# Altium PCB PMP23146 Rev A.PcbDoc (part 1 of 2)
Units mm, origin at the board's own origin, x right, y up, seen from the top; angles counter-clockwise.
Board outline 35 x 30 mm, 4 copper layers (Top Layer, Int1 (GND), Int2 (PWR), Bottom Layer), stack 0.912 mm thick; 72 components, 51 nets, 255 pads, 53 vias.
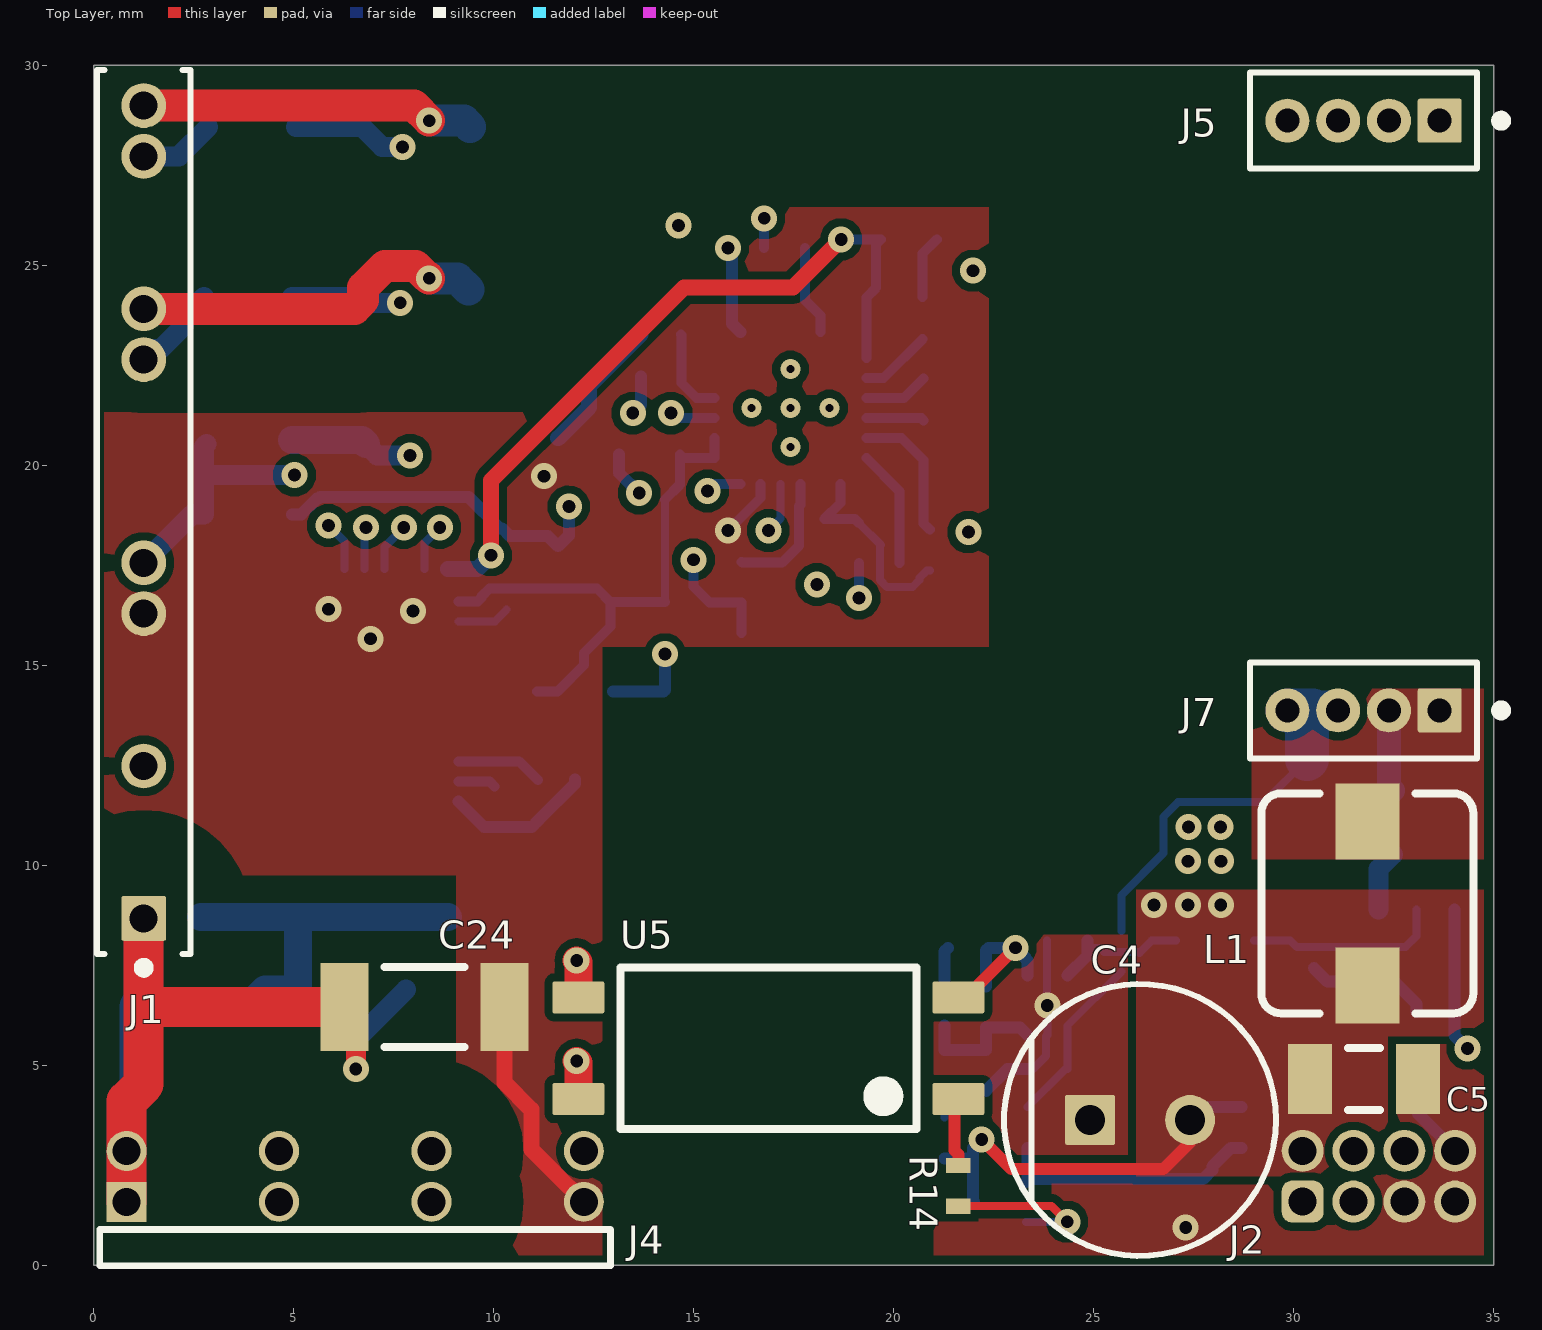
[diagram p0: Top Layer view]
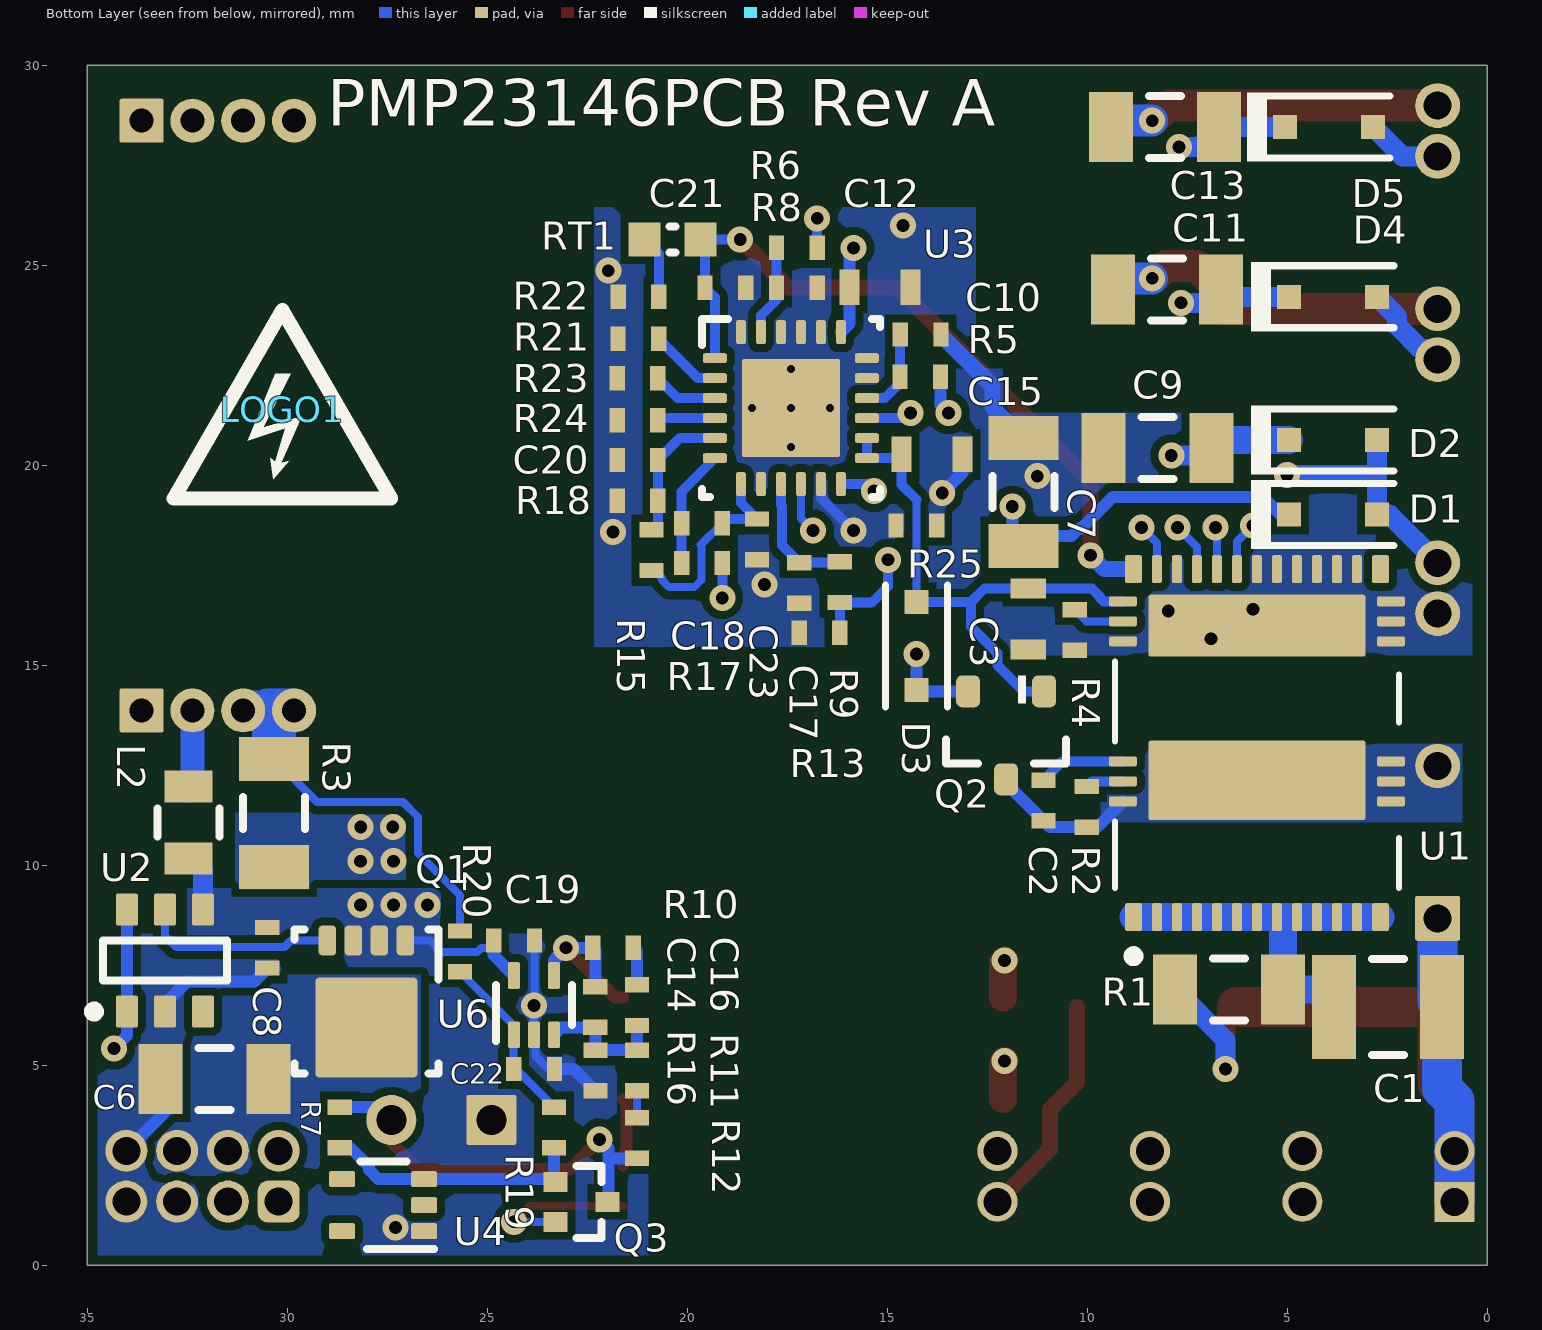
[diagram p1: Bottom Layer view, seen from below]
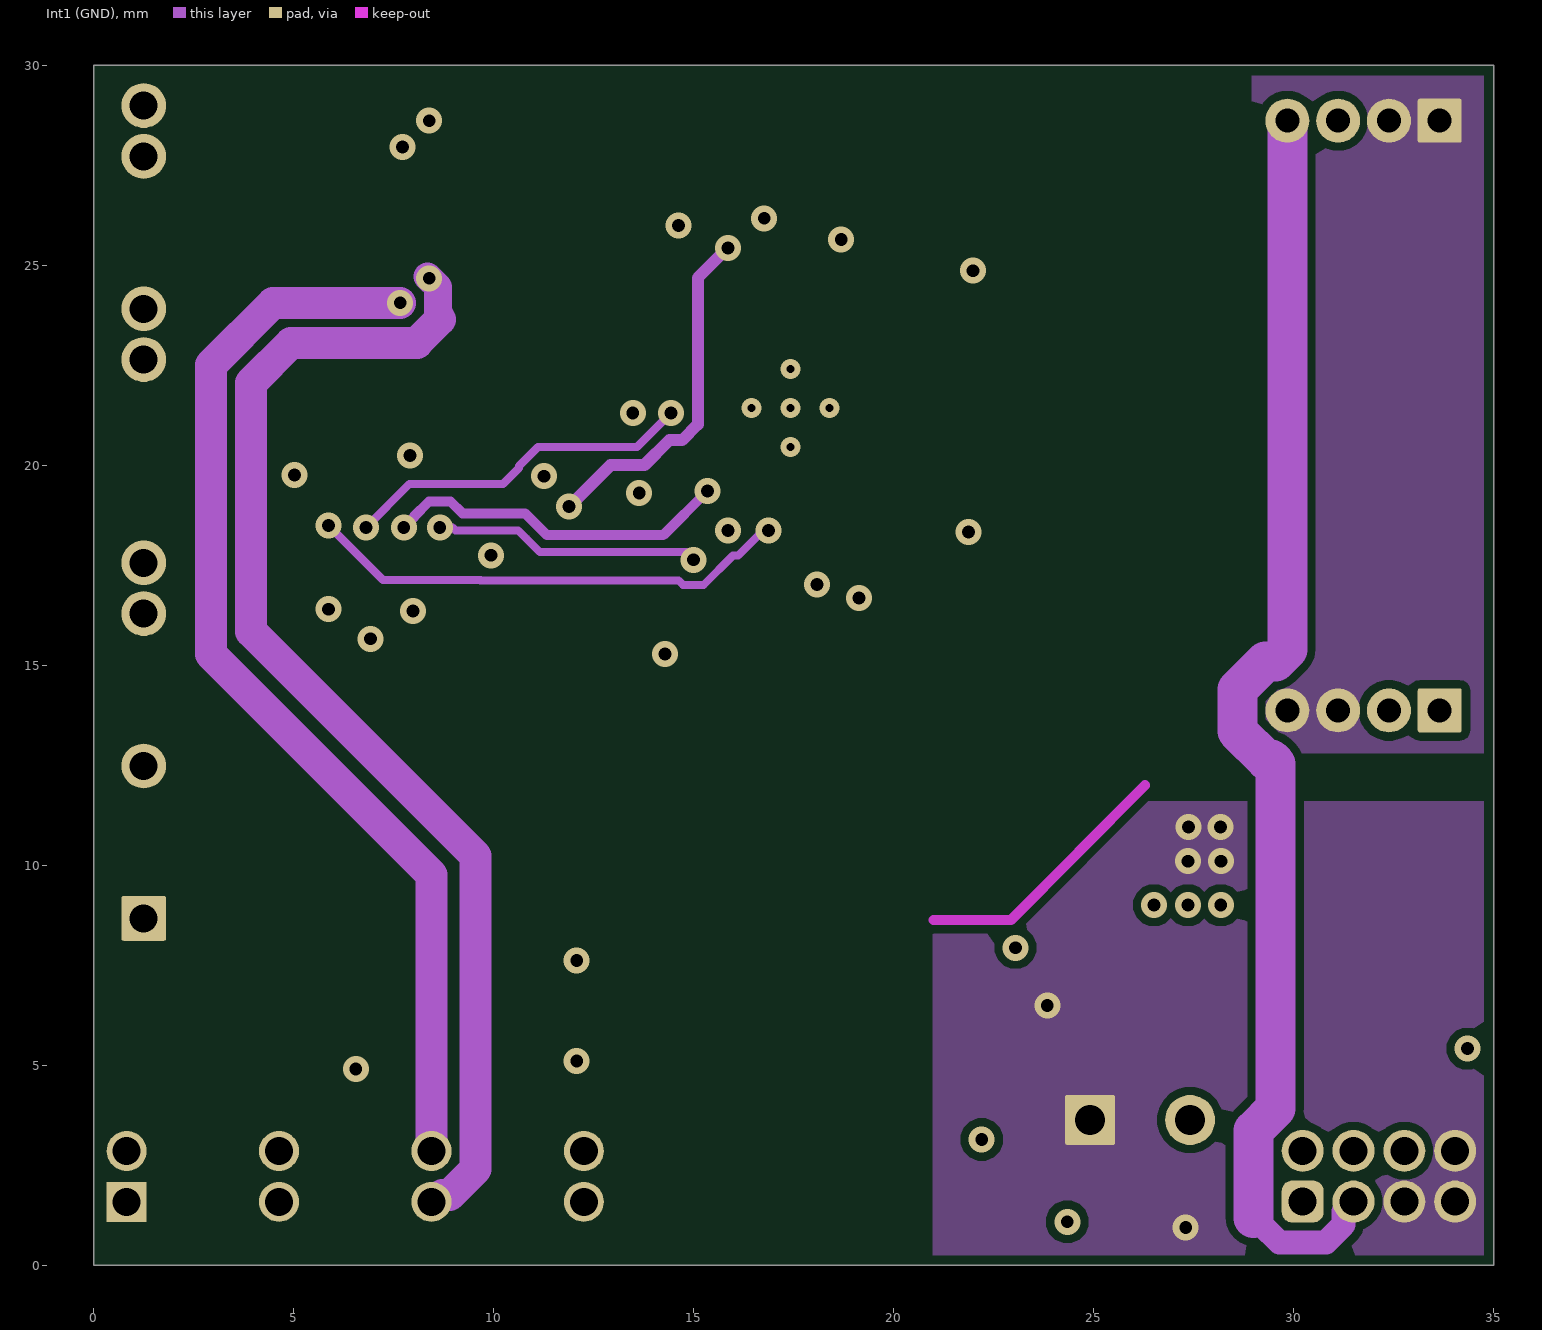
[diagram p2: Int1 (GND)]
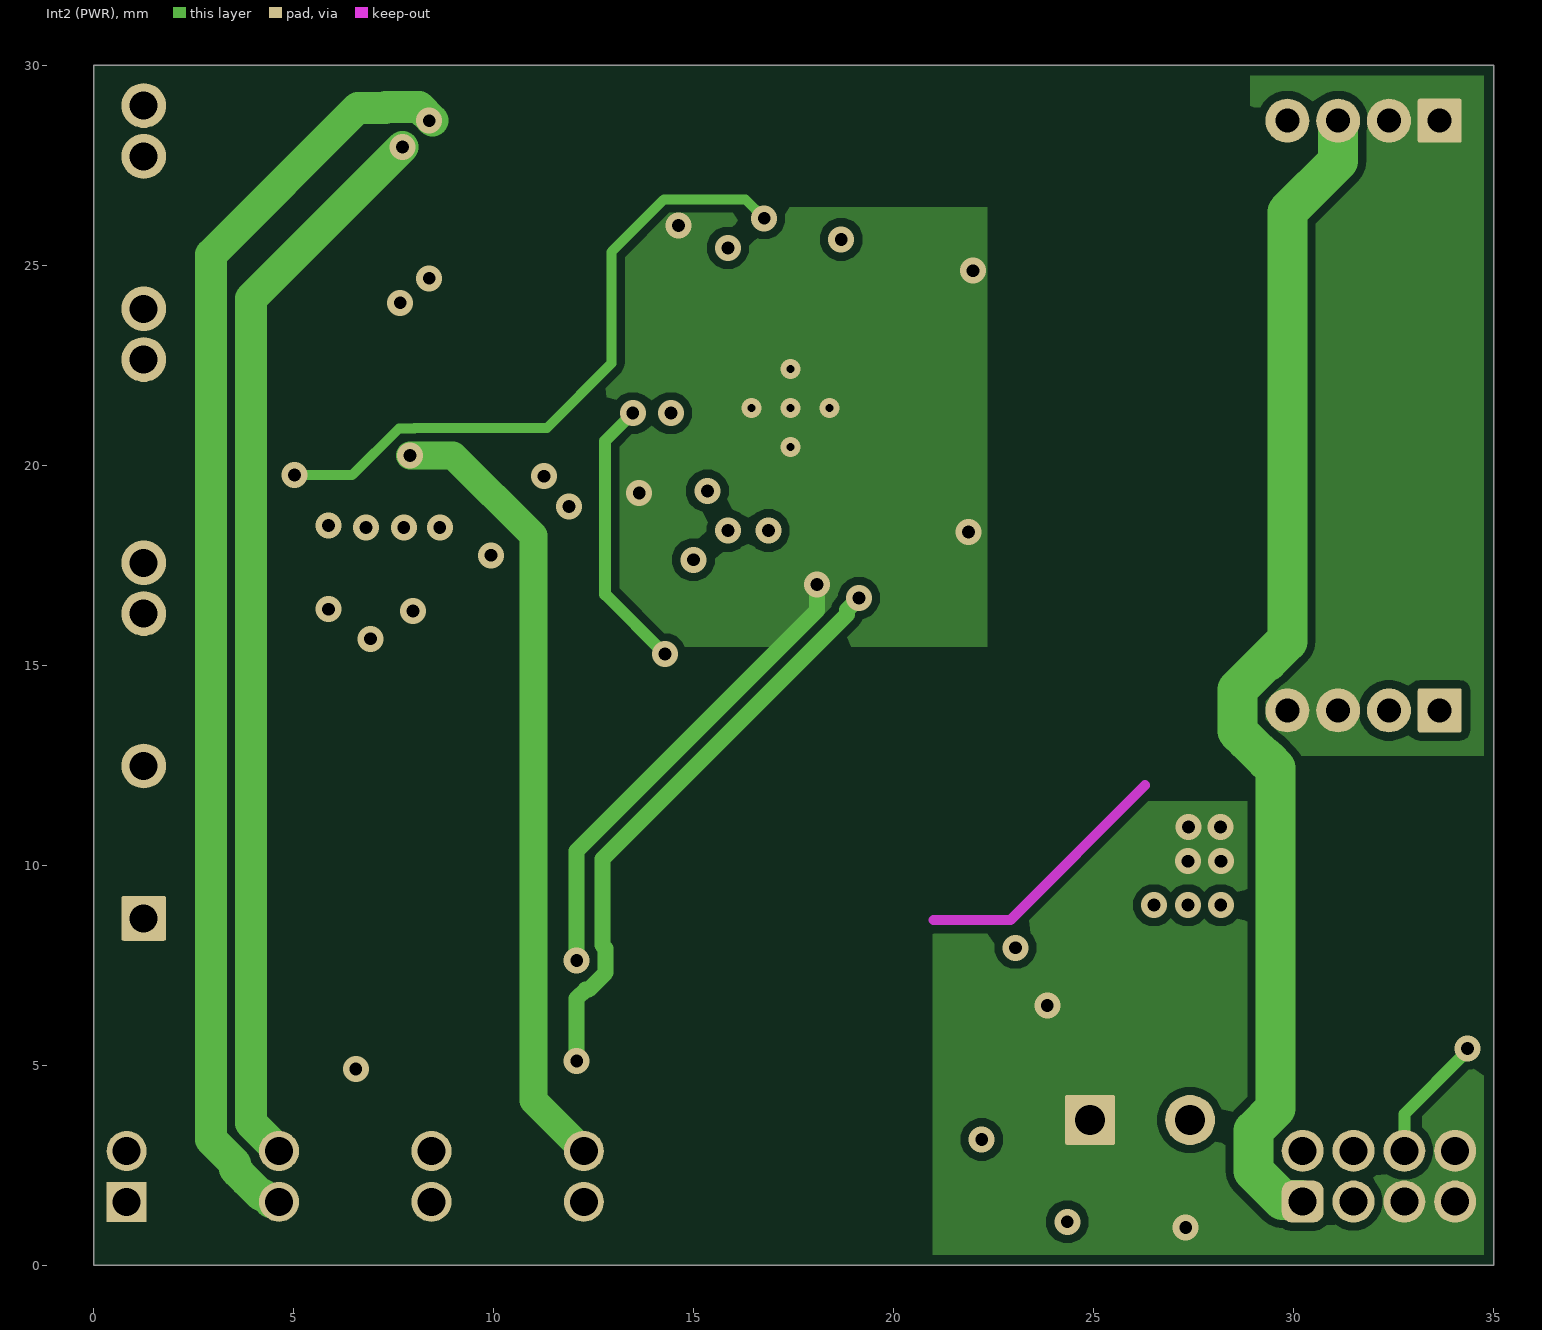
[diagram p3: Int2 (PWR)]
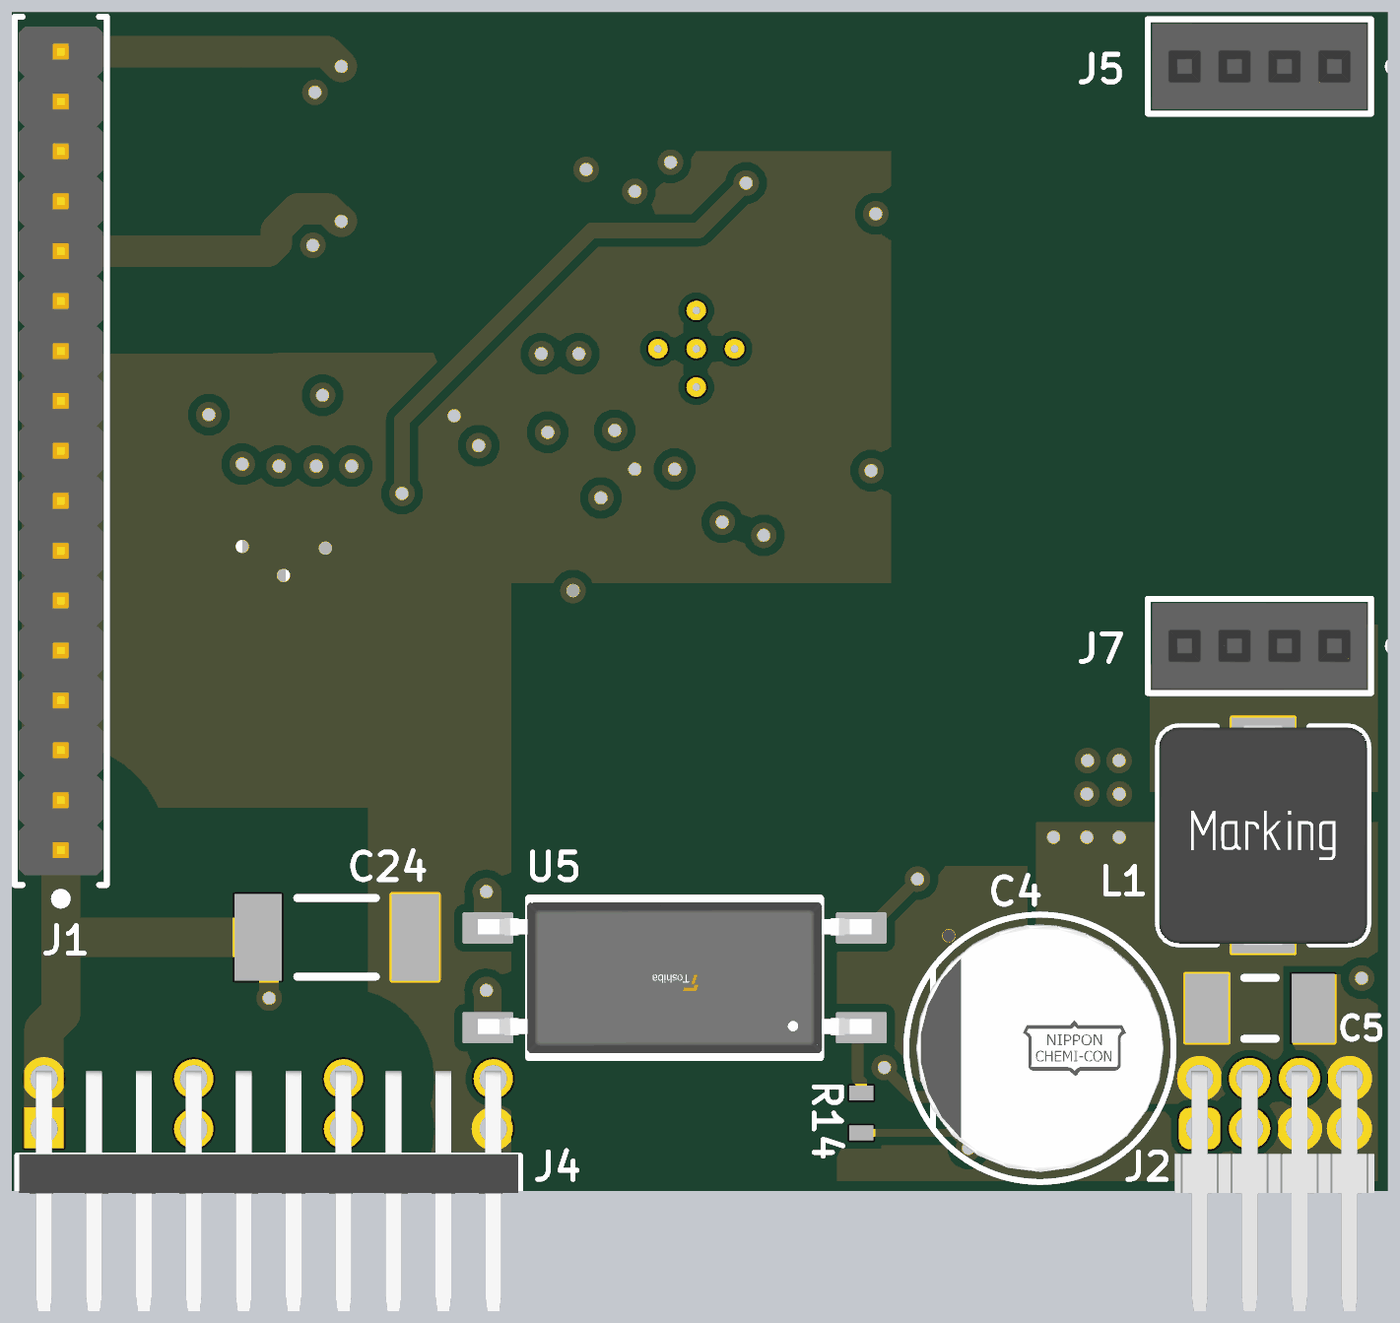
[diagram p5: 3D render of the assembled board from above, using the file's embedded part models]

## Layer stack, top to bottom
Top Solder: solder mask 0.0254, SM-001, Dk 4
Top Layer: signal copper 0.035
Dielectric 1: prepreg 0.1295, PP-017, Dk 4.3
Dielectric 2: prepreg 0.1295, PP-017, Dk 4.3
Int1 (GND): signal copper 0.035
Dielectric 3: core 0.254, Core-028, Dk 4.3
Int2 (PWR): signal copper 0.035
Dielectric 4: prepreg 0.1295, PP-017, Dk 4.3
Dielectric 5: prepreg 0.1295, PP-017, Dk 4.3
Bottom Layer: signal copper 0.035
Bottom Solder: solder mask 0.0254, SM-001, Dk 4

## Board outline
0,0 35,0 35,30 0,30

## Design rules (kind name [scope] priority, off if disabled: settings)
AcuteAngle [All] p1: minimum=5.00000000000000E+0000 checktracksonly=FALSE
AssemblyTestPointUsage [All] p1: valid=2
BoardOutlineClearance BoardOutlineClearance_Pri [InNet('P')] p1: gap=0.4 ignorepadtopadclearanceinfootprint=FALSE
BoardOutlineClearance BoardOutlineClearance_MountingHoles [OnCopper and InComponentClass('Mounting Holes')] p2: gap=0.635 ignorepadtopadclearanceinfootprint=FALSE
BoardOutlineClearance BoardOutlineClearance_Poly [OnCopper and InPoly] p3: gap=0.25 ignorepadtopadclearanceinfootprint=FALSE
BoardOutlineClearance [OnCopper and Not InComponentClass('Logo') and not InComponentClass('FiducialMark') and not InRegion(1000,500,4000,800)] p4: gap=0.25 ignorepadtopadclearanceinfootprint=FALSE
Clearance "Pri To Sec Inner Layers" [InNet('S') vs InNet('A')  Or InNet('B')] p1: gap=0.5 ignorepadtopadclearanceinfootprint=TRUE
Clearance "400V Clearance" [(InNetClass('400V') AND (OnTopLayer Or OnBottomLayer)) vs (InNetClass('Primary LV'))] p2: gap=2.2 ignorepadtopadclearanceinfootprint=TRUE
Clearance "Float Bias Clearance" [(InNetClass('BIAS_FLOAT') AND (OnTopLayer Or OnBottomLayer)) vs (InNetClass('Primary LV'))] p3: gap=2.2 ignorepadtopadclearanceinfootprint=TRUE
Clearance Clearance_Keepouts [((IsTrack Or IsArc) And Not InPoly) And IsFree and IsKeepOut vs ((IsTrack Or IsArc) And Not InPoly) And IsFree and IsKeepOut] p4: gap=0 ignorepadtopadclearanceinfootprint=TRUE
Clearance Clearance_Poly [InPolygon] p5: gap=0.203 ignorepadtopadclearanceinfootprint=TRUE except(0: Arc-Hole Track-Hole SMDPad-Hole THPad-Hole Via-Hole Fill-Hole Poly-Hole Region-Hole Text-Hole)
Clearance [All] p6: gap=0.2 ignorepadtopadclearanceinfootprint=TRUE except(0: Arc-Hole Track-Hole SMDPad-Hole THPad-Hole Via-Hole Fill-Hole Poly-Hole Region-Hole Text-Hole)
ComponentClearance ComponentClearance_MountingHoles_FiducialMarks [InComponentClass('Mounting Holes') vs InComponentClass('FiducialMark')] p1: gap=1.27 collisioncheckmode=3 verticalgap=0.254 showdistances=FALSE
ComponentClearance ComponentClearance_Shunt [InComponentClass('Header') vs InComponentClass('Shunt')] p2: gap=0 collisioncheckmode=3 verticalgap=0 showdistances=FALSE
ComponentClearance ComponentClearance_Logo [InComponentClass('Logo')] p3: gap=1.27 collisioncheckmode=3 verticalgap=0.254 showdistances=FALSE
ComponentClearance ComponentClearance_ScrewToNut [(HasFootprint('NY PMS 440 0025 PH')) vs (HasFootprint('Keystone_1902C'))] p4: gap=0.127 collisioncheckmode=3 verticalgap=0.254 showdistances=FALSE
ComponentClearance ComponentClearance_MountingHoles [InComponentClass('Mounting Holes')] p5: gap=6.35 collisioncheckmode=3 verticalgap=2540 showdistances=FALSE
ComponentClearance ComponentClearance_SmallPassives [HasFootprint('0201*') or HasFootprint('0402*') or HasFootprint('0508') or HasFootprint('0603*') or HasFootprint('0612') or HasFootprint('0805*') or HasFootprint('0815*') or HasFootprint('0830*') or HasFootprint('1206*') or HasFootprint('1210*') or HasFootprint('1808*') or HasFootprint('1812*') or HasFootprint('1825*') or HasFootprint('2010*') or HasFootprint('2220*') or HasFootprint('2225*') or HasFootprint('2512*') or HasFootprint('2728*') or HasFootprint('3518*') vs HasFootprint('0201*') or HasFootprint('0402*') or HasFootprint('0508') or HasFootprint('0603*') or HasFootprint('0612') or HasFootprint('0805*') or HasFootprint('0815*') or HasFootprint('0830*') or HasFootprint('1206*') or HasFootprint('1210*') or HasFootprint('1808*') or HasFootprint('1812*') or HasFootprint('1825*') or HasFootprint('2010*') or HasFootprint('2220*') or HasFootprint('2225*') or HasFootprint('2512*') or HasFootprint('2728*') or HasFootprint('3518*')] p6: gap=0.38 collisioncheckmode=3 verticalgap=0.254 showdistances=FALSE
ComponentClearance ComponentClearance_THtoSMT [IsThruComponent vs IsSMTComponent] p7: gap=0.381 collisioncheckmode=3 verticalgap=0.762 showdistances=FALSE
ComponentClearance ComponentClearance_THtoTH [IsThruComponent vs IsThruComponent] p8: gap=0.381 collisioncheckmode=3 verticalgap=0.762 showdistances=FALSE
ComponentClearance [All] p9: gap=0.381 collisioncheckmode=3 verticalgap=0.254 showdistances=FALSE
DiffPairsRouting [All] p1: maxlimit=2.54 minlimit=0.254 mostfreqgap=0.254 toplayer_minwidth=0.381 toplayer_maxwidth=0.381 toplayer_prefwidth=0.381 midlayer1_minwidth=0.381 midlayer1_maxwidth=0.381 midlayer1_prefwidth=0.381 midlayer2_minwidth=0.381 midlayer2_maxwidth=0.381 midlayer2_prefwidth=0.381 bottomlayer_minwidth=0.381 bottomlayer_maxwidth=0.381 bottomlayer_prefwidth=0.381 maxuncoupledlength=25.4
FabricationTestPointUsage TestPointUsage [All] p1: valid=2 allowmultiple=FALSE
FabricationTestpoint Testpoint [All] p1: side=3 testpointundercomponent=TRUE minsize=1.016 maxsize=2.54 preferedsize=1.524 minholesize=0 maxholesize=1.016 preferedholesize=0.813 testpointgrid=0.025 allowsidetop=TRUE allowsidebottom=TRUE usegrid=TRUE gridtolerance=0
FanoutControl Fanout_LCC [IsLCC] p1: bgadir=Out bgaviamode=Centered fanoutstyle=Auto fanoutdirection=Alternating viagrid=0.025 // Fanout_LCC (Default Rule)
FanoutControl Fanout_BGA [IsBGA] p2: bgadir=Out bgaviamode=Centered fanoutstyle=Auto fanoutdirection=Alternating viagrid=0.025 // Fanout_BGA (Default Rule)
FanoutControl Fanout_Default [All] p4: bgadir=Out bgaviamode=Centered fanoutstyle=Auto fanoutdirection=Alternating viagrid=0.025 // Fanout_Default (Default Rule)
FanoutControl Fanout_Small [(CompPinCount < 5)] p5: bgadir=Out bgaviamode=Centered fanoutstyle=Auto fanoutdirection=OutThenIn viagrid=0.025 // Fanout_Small (Default Rule)
HoleSize [All] p1: absolutevalues=TRUE maxlimit=6.375 minlimit=0.2 maxpercent=80.000 minpercent=20.000
MinimumAnnularRing MinimumAnnularRing_ThermalPadVias [IsVia and InAnyComponent] p1: minimumring=0.15
MinimumAnnularRing [All] p2: minimumring=0.15
MinimumSolderMaskSliver MinimumSolderMaskSliver_Logo [InComponentClass('Logo') vs InComponentClass('Logo')] p1 off: minsoldermaskwidth=0.018
MinimumSolderMaskSliver [All] p2 off: minsoldermaskwidth=0.025
PlaneConnect [All] p1: planeconnectstyle=Direct reliefexpansion=0.254 reliefentries=4 reliefconductorwidth=0.254 reliefairgap=0.254
PolygonConnect [All] p1: connectstyle=Direct reliefconductorwidth=0.381 reliefentries=4 polygonreliefangle="90 Angle" airgapwidth=0.254
RoutingVias ThermalPadVias [IsVia and InAnyComponent] p1: holewidth=0.2 width=0.5 viastyle="Through Hole" minholewidth=0.2 minwidth=0.5 maxholewidth=0.33 maxwidth=0.6
RoutingVias [All] p2: holewidth=0.406 width=0.864 viastyle="Through Hole" minholewidth=0.2 minwidth=0.65 maxholewidth=1.016 maxwidth=1.651
SilkToBoardRegionClearance [Not ((IsComment or IsDesignator) And (Hide <> 'False')) and not InRegion(1000,500,4000,800)] p1:
SilkToSilkClearance SilkToSilkClearance_Pb-FreeLogo [(HasFootprint('Pb-Free_Overlay_Medium') OR HasFootprint('Pb-Free_Overlay_Small')) vs (HasFootprint('Pb-Free_Overlay_Medium') OR HasFootprint('Pb-Free_Overlay_Small'))] p1: silktosilkclearance=0
SilkToSilkClearance [All] p2: silktosilkclearance=0.025
SilkToSolderMaskClearance SilkToComponentPadClearance [IsPad and InAnycomponent] p1: minsilkscreentomaskgap=0 clearancetoexposedcopper=TRUE
SilkToSolderMaskClearance "Silk to Solder Mask Opening" [All] p2: minsilkscreentomaskgap=0 clearancetoexposedcopper=FALSE
SolderMaskExpansion [All] p1: expansion=0.05 istentingtop=FALSE
Width [All] p1: maxlimit=4 minlimit=0.152 preferedwidth=0.254 checkconnectedcopper=TRUE
15 further rules are at their usual default settings.

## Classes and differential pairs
net class "Primary LV": PWRGND
net class BIAS_FLOAT: NetD4_2 NetD5_2 P12V_ISO1 P12V_ISO1_RTN P12V_ISO2 P12V_ISO2_RTN
net class 400V: NetC1_2 VDCIN VSWN
component class Header: J2

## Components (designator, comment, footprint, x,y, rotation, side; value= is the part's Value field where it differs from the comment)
C1 "C1210C334KARACAUTO" 1210_220L 2.487,6.46 r0 bottom value=0.33uF
C2 "GRM155R71H223KA12D" 0402S 11.099,11.623 r270 bottom value=0.022uF
C3 "C1608X7R1E105K080AB" 0603S 11.484,16.16 r90 bottom value=1uF
C4 "APSG160ELL271MF08J" FP-APSG160ELL271MF08J_RADIAL-MFG 26.153,3.636 r0 top value=270µF
C5 "C3216X5R1V226M160AC" 1206_180L 31.752,4.654 r180 top value=22uF
C6 "C3216X5R1V226M160AC" 1206_180L 31.819,4.654 r0 bottom value=22uF
C7 "C3216X5R1V226M160AC" 1206_180L 11.603,19.329 r90 bottom value=22uF
C8 "GRM155R71E104KE14D" 0402S 30.5,7.941 r270 bottom value=0.1uF
C9 "C3216X5R1V226M160AC" 1206_180L 8.246,20.434 r0 bottom value=22uF
C10 "GRM1555C1H220JA01D" 0402S 14.17,23.272 r0 bottom value=22pF
C11 "C3216X5R1V226M160AC" 1206_180L 8.015,24.397 r0 bottom value=22uF
C12 "GRM188R6YA106MA73D" 0603S 15.186,24.449 r180 bottom value=10uF
C13 "C3216X5R1V226M160AC" 1206_180L 8.057,28.46 r0 bottom value=22uF
C14 "GRM1555C1H101JA01D" 0402S 22.3,6.46 r270 bottom value=100pF
C15 "C1608X7R1E105K080AB" 0603S 13.886,20.274 r0 bottom value=1uF
C16 "GRM155R71E104KE14D" 0402S 21.26,6.506 r90 bottom value=0.1uF
C17 "GRM1555C1H101JA01D" 0402S 17.202,17.061 r270 bottom value=100pF
C18 "GRM155R71H331KA01D" 0402S 19.636,18.555 r180 bottom value=330pF
C19 "GRM155R71E104KE14D" 0402S 24.334,8.122 r0 bottom value=0.1uF
C20 "GRM155R71H331KA01D" 0402S 21.249,20.134 r180 bottom value=330pF
C21 "GRM1555C1H101JA01D" 0402S 19.049,24.444 r180 bottom value=100pF
C22 "GCM155R71E103KA37D" 0402S 23.834,4.911 r180 bottom value=0.01uF
C23 "GRM155R71C224KA12D" 0402S 18.26,18.149 r270 bottom value=0.22uF
C24 "C1808W104KBRACTU" 1808_215_L 8.261,6.46 r0 top value=0.1uF
D1 "BAS20HT1G" SOD-323 3.857,18.769 r180 bottom value=200V
D2 "BAS20HT1G" SOD-323 3.857,20.632 r180 bottom value=200V
D3 "DF2B18FU" SOD-323-Bi 14.276,15.481 r90 bottom value=16.2V
D4 "BAS20HT1G" SOD-323 3.857,24.216 r180 bottom value=200V
D5 "BAS20HT1G" SOD-323 3.957,28.46 r180 bottom value=200V
J1 "LPPB171NFFN-RC" FP-GRPB171VWVN-RC_HDR17-MFG 1.245,18.836 r90 top
J2 "GRPB042MWCN-RC" Sullins_GRPB042MWCN 32.123,2.231 r90 top
J4 "GRPB102MWCN-RC" Sullins_GRPB102MWCN-modified 6.532,2.225 r0 top
J5 "LPPB041NFFN-RC" FP-LPPB041NFFN-RC_HDR04-MFG 31.74,28.617 r180 top
J7 "LPPB041NFFN-RC" FP-LPPB041NFFN-RC_HDR04-MFG 31.74,13.875 r180 top
L1 "744316100" WE-HCI_5040 31.833,9.053 r0 top value=1uH
L2 "MLP2012S1R0MT0S1" MLP2012S-M 32.477,11.073 r270 bottom value=1uH
LOGO1 "DANGER HIGH VOLTAGE" IEC_HighVoltage_Small 30.126,21.407 r180 bottom
Q1 "CSD17575Q3" DQG0008A_NV 28.025,6.597 r270 bottom value=30V
Q2 "BSS126" SOT-23L 12.031,13.25 r270 bottom value=600V
Q3 "DTC114EET1G" SOT-416 22.648,1.59 r180 bottom value="50 V"
R1 "CRCW12063M30JNEA" 1206L 6.457,6.899 r0 bottom value=3.3Meg
R2 "CRCW04020000Z0EDHP" 0402S 10.015,11.465 r90 bottom value=0
R3 "CSR1206FK10L0" 1206L 30.331,11.306 r270 bottom value=0.01
R4 "CRCW04020000Z0EDHP" 0402S 10.315,15.885 r90 bottom value=0
R5 "CRCW0402511RFKED" 0402S 14.18,22.218 r180 bottom value=511
R6 "CRCW040232K4FKED" 0402S 17.264,25.438 r180 bottom value=32.4k
R7 "CRCW040210K0FKED" 0402S 28.688,3.449 r90 bottom value=10.0k
R8 "CRCW04029K31FKED" 0402S 17.264,24.444 r0 bottom value=9.31k
R9 "CRCW0402511RFKED" 0402S 16.19,17.083 r90 bottom value=511
R10 "CRCW040210K0FKED" 0402S 21.861,7.941 r0 bottom value=10.0k
R11 "CRCW040210K0FKED" 0402S 21.26,4.874 r90 bottom value=10.0k
R12 "RC0402JR-070RL" 0402S 21.26,3.184 r90 bottom value=0
R13 "CRCW0402150RFKED" 0402S 16.698,15.816 r180 bottom value=150
R14 "CRCW04024K99FKED" 0402S 21.61,1.99 r270 top value=4.99k
R15 "CRCW0402200KFKED" 0402S 20.899,17.884 r270 bottom value=200k
R16 "CRCW04024K42FKED" 0402S 22.297,4.874 r90 bottom value=4.42k
R17 "CRCW040220K0FKED" 0402S 19.636,17.561 r180 bottom value=20.0k
R18 "CRCW040241K2FKED" 0402S 21.249,19.119 r180 bottom value=41.2k
R19 "CRCW0402100KFKED" 0402S 23.334,3.449 r270 bottom value=100k
R20 "CRCW0402309KFKED" 0402S 25.686,7.85 r270 bottom value=309k
R21 "CRCW0402200KFKED" 0402S 21.227,23.162 r180 bottom value=200k
R22 "CRCW04020000Z0ED" 0402S 21.224,24.216 r180 bottom value=0
R23 "CRCW040290K9FKED" 0402S 21.249,22.176 r180 bottom value=90.9k
R24 "CRCW04020000Z0ED" 0402S 21.249,21.129 r180 bottom value=0
R25 "CRCW04020000Z0ED" 0402S 14.276,18.499 r180 bottom value=0
RT1 "CRCW060346K4FKEA" 0603L 20.375,25.654 r0 bottom value=46.4k
U1 "LMG2610RRGT" RRG0038A-MFG 5.761,13.057 r90 bottom
U2 "LM5050MK-1/NOPB" DDC0006A_L 33.062,7.622 r90 bottom
U3 "UCC28782RTW" RTW0024B 17.411,21.434 r180 bottom
U4 "LM4040D50IDCKR" DCK0005A_L 27.608,1.506 r0 bottom
U5 "TLP383(GR-TPL,E" FP-TLP383(GR-TPL,E_SO6-4-MFG 16.86,5.429 r180 top
U6 "OPA170AIDRLT" DRL0005A 23.834,6.506 r90 bottom

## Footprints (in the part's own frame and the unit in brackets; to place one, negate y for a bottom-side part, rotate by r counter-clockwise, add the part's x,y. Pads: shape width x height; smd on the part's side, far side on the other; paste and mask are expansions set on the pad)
0402S [mil] "Based on C0402S footprint from PADS legacy"
  rect 15x24 smd: 1(-20,0) 2(20,0)
  body extent -22,-12 22,12, height 24
0603L [mm] "0603 from SM-752 data"
  rect 0.8x0.85 smd: 1(-0.7,0) 2(0.7,0)
  silkscreen extent -0.07,-0.33 0.07,0.33, body extent -0.87,-0.47 0.87,0.47, height 1
0603S [mil]
  rect 20x35 smd: 1(-30,0) 2(30,0)
  body extent -34,-19 34,19, height 39
1206_180L [mm] "1206_180"
  rect 1.1x1.75 smd: 1(-1.35,0) 2(1.35,0)
  silkscreen extent -0.4,-0.77 0.4,0.77, body extent -1.75,-0.95 1.75,0.95, height 1.8
1206L [mm] "1206 from SM-752 data"
  rect 1.1x1.75 smd: 1(-1.35,0) 2(1.35,0)
  silkscreen extent -0.4,-0.77 0.4,0.77, body extent -1.7,-0.9 1.7,0.9, height 1.35
1210_220L [mm] "1210"
  rect 1.1x2.6 smd: 1(-1.35,0) 2(1.35,0)
  silkscreen extent -0.4,-1.2 0.4,1.2, body extent -1.7,-1.35 1.7,1.35, height 2.2
1808_215_L [mm] "Chip Capacitor, Body 4.6x2.0mm, IPC High Density"
  rect 1.2x2.2 smd: 1(-2,0) 2(2,0)
  silkscreen extent -1,-1 1,1, body extent -2.47,-1.2 2.47,1.2, height 2.15
DCK0005A_L [mm] "SOT353, 5-Leads, Body 2x1.3mm, Pitch 0.65mm, Lead Span 2.1mm, IPC High Density"
  rrect25% 0.65x0.4 smd: 1(-1.025,0.65) 2(-1.025,0) 3(-1.025,-0.65) 4(1.025,-0.65) 5(1.025,0.65)
  silkscreen extent -1.27,-1.09 0.56,1.09, body extent -1.14,-1 1.14,1, height 0.95
DDC0006A_L [mm] "SOT23, 6-Leads, Body 3.05x1.75mm, Pitch 0.95mm, IPC High Density"
  rrect18% 0.8x0.55 smd: 1(-1.275,0.95) 2(-1.275,0) 3(-1.275,-0.95) 4(1.275,-0.95) 5(1.275,0) 6(1.275,0.95)
  silkscreen extent -1.4,-1.55 0.5,1.9, body extent -1.43,-1.48 1.43,1.49, height 0.9
DQG0008A_NV [mm] "SMD, 8-Leads, Body 3.3x3.3mm, Pitch 0.65mm"
  rrect45% 0.75x0.44 smd paste-0.05 mask-0.05: 1(-1.525,0.975) 2(-1.525,0.325) 3(-1.525,-0.325) 4(-1.525,-0.975) 5(1.525,-0.975) 6(1.525,-0.325) 7(1.525,0.325) 8(1.525,0.975)
  rrect15% 0.676x1.125 on Bottom Paste: 9(-0.212,-0.663) 9(-0.212,0.662) 9(0.664,-0.663) 9(0.664,0.662)
  rrect6% 1.775x2.45 on Bottom Solder: 9(0.327,0)
  rrect8% 2.5x2.55 smd paste-1.5 mask-1.5: 9(0.65,0)
  rrect29% 0.5x0.34 on Bottom Solder: 9(1.175,-0.975) 9(1.175,-0.325) 9(1.175,0.325) 9(1.175,0.975)
  silkscreen extent -1.8,-1.8 1.8,1.8, body extent -1.65,-1.65 1.65,1.65, height 1.1
DRL0005A [mm] "SOTFL, 5-Flat Leads, Body 1.2x1.6x0.6mm, Pitch 0.5mm, TI recommended"
  rrect33% 0.67x0.3 smd: 1(-0.74,0.5) 2(-0.74,0) 3(-0.74,-0.5) 4(0.74,-0.5) 5(0.74,0.5)
  silkscreen extent -0.9,-0.95 0.5,0.95, body extent -0.85,-0.85 0.85,0.85, height 0.62
FP-APSG160ELL271MF08J_RADIAL-MFG [mm]
  rrect8% 1.25x1.25 hole 0.75 paste-1000 mask+0: 1(-1.25,0)
  round 1.25 hole 0.75 paste-1000 mask+0: 2(1.25,0)
  silkscreen extent -3.4,-3.4 3.4,3.4, body extent -3.5,-3.5 3.5,3.5, height 0.25
FP-GRPB171VWVN-RC_HDR17-MFG [mm]
  rrect9% 1.12x1.12 hole 0.7 paste-1000 mask+0: 1(-10.16,0)
  round 1.12 hole 0.7 paste-1000 mask+0: 4(-6.35,0) 7(-2.54,0) 8(-1.27,0) 12(3.81,0) 13(5.08,0) 16(8.89,0) 17(10.16,0)
  silkscreen extent -11.52,-1.17 11.04,1.17, body extent -11.14,-1.27 11.14,1.27, height 0.25
FP-LPPB041NFFN-RC_HDR04-MFG [mm]
  rrect9% 1.1x1.1 hole 0.6 paste-1000 mask+0: 1(-1.905,0)
  round 1.1 hole 0.6 paste-1000 mask+0: 2(-0.635,0) 3(0.635,0) 4(1.905,0)
  silkscreen extent -3.57,-1.2 2.84,1.2, body extent -2.94,-1.3 2.94,1.3, height 0.25
FP-TLP383(GR-TPL,E_SO6-4-MFG [mm]
  rrect13% 1.3x0.8 smd paste+0 mask+0: 1(-4.75,1.27) 3(-4.75,-1.27) 4(4.75,-1.27) 6(4.75,1.27)
  silkscreen extent -3.7,-2.02 3.7,2.02, body extent -5.5,-2.12 5.5,2.12, height 0.25
IEC_HighVoltage_Small [mm]
  silkscreen extent -2.72,-2.24 2.72,2.47
MLP2012S-M [mm] "TDK"
  rect 0.8x1.2 smd: 1(-0.9,0) 2(0.9,0)
  silkscreen extent -0.35,-0.77 0.35,0.77, body extent -1.1,-0.72 1.1,0.72, height 1
RRG0038A-MFG [mm]
  rrect24% 0.7x0.425 smd paste+0 mask-1000: 1(-4.35,3.087) 13(-4.35,-3.087) 20(4.35,-3.087) 32(4.35,3.087)
  rrect40% 0.7x0.25 smd paste+0 mask+0: 2(-4.35,2.5) 3(-4.35,2) 4(-4.35,1.5) 5(-4.35,1) 6(-4.35,0.5) 7(-4.35,0) 8(-4.35,-0.5) 9(-4.35,-1) 10(-4.35,-1.5) 11(-4.35,-2) 12(-4.35,-2.5) 21(4.35,-2.5) 22(4.35,-2) 23(4.35,-1.5) 24(4.35,-1) 25(4.35,-0.5) 26(4.35,0)
  rrect40% 0.25x0.7 smd paste+0 mask-1000: 14(-1.455,-3.35) 17(2.545,-3.35) 33(3.545,3.35) 34(3.045,3.35) 35(2.545,3.35) 36(-0.455,3.35) 37(-0.955,3.35) 38(-1.455,3.35)
  rrect40% 0.25x0.7 smd paste+0 mask+0: 15(-0.955,-3.35) 16(-0.455,-3.35) 18(3.045,-3.35) 19(3.545,-3.35)
  rrect40% 0.7x0.25 smd paste+0 mask-1000: 27(4.35,0.5) 28(4.35,1) 29(4.35,1.5) 30(4.35,2) 31(4.35,2.5)
  rrect5% 1.99x5.42 smd paste-1000 mask+0: 39(-0.93,0)
  rrect6% 1.55x5.42 smd paste-1000 mask+0: 40(2.935,0)
  silkscreen extent -5.45,-3.55 2.04,3.55, body extent -4.5,-3.5 4.5,3.5, height 1
RTW0024B [mm] "QFN, 24-Leads, Body 4x4mm, Pitch 0.5mm, Thermal Pad 2.45x2.45mm, TI Recommended"
  rrect42% 0.6x0.24 smd: 1(-1.9,1.25) 2(-1.9,0.75) 3(-1.9,0.25) 4(-1.9,-0.25) 5(-1.9,-0.75) 6(-1.9,-1.25) 13(1.9,-1.25) 14(1.9,-0.75) 15(1.9,-0.25) 16(1.9,0.25) 17(1.9,0.75) 18(1.9,1.25)
  rrect42% 0.24x0.6 smd: 7(-1.25,-1.9) 8(-0.75,-1.9) 9(-0.25,-1.9) 10(0.25,-1.9) 11(0.75,-1.9) 12(1.25,-1.9) 19(1.25,1.9) 20(0.75,1.9) 21(0.25,1.9) 22(-0.25,1.9) 23(-0.75,1.9) 24(-1.25,1.9)
  rrect4% 2.45x2.45 smd paste-1.225: 25(0,0)
  silkscreen extent -2.22,-2.22 2.22,2.22, body extent -2.07,-2.07 2.07,2.07, height 0.81
SOD-323 [mm] "NXP recommended land pattern"
  rect 0.6x0.6 smd paste-0.05: 1(-1.1,0) 2(1.1,0)
  silkscreen extent -2.06,-0.86 1.53,0.86, body extent -1.3,-0.67 1.3,0.68, height 1.1
SOD-323-Bi [mm] "SOD323, 2-Leads, Body 1.9x1.45mm, No Polarity Mark"
  rect 0.6x0.6 smd paste-0.05: 1(-1.1,0) 2(1.1,0)
  silkscreen extent -1.53,-0.77 1.53,0.77, body extent -1.27,-0.65 1.27,0.65, height 1.02
SOT-23L [mm] "SOT23, 3-Leads, Body 2.9x1.3mm, Pitch 0.95mm, Lead Span 2.5mm, IPC High Density"
  rrect50% 0.8x0.6 smd: 1(-1.1,0.95) 2(-1.1,-0.95) 3(1.1,0)
  silkscreen extent -1.5,-1.5 0.7,1.5, body extent -1.16,-1.45 1.21,1.45, height 1
SOT-416 [mm] "NXP recommended footprint."
  rect 0.6x0.5 smd: 1(-0.65,0.5) 2(-0.65,-0.5) 3(0.65,0)
  silkscreen extent -0.13,-0.9 0.5,0.9, body extent -0.8,-0.9 0.8,0.9, height 0.82
Sullins_GRPB042MWCN [mm] "Header, 1.27mm, 4x2, R/A, TH"
  rrect50% 1.05x1.05 hole 0.7: 1(-0.635,1.905)
  round 1.05 hole 0.7: 2(0.635,1.905) 3(-0.635,0.635) 4(0.635,0.635) 5(-0.635,-0.635) 6(0.635,-0.635) 7(-0.635,-1.905) 8(0.635,-1.905)
  body extent -5.28,-2.54 0.84,2.54, height 3.4
Sullins_GRPB102MWCN-modified [mm] "SULLINS"
  rect 1x1 hole 0.7: 1(-5.715,-0.635)
  round 1 hole 0.7: 2(-5.715,0.635) 7(-1.905,-0.635) 8(-1.905,0.635) 13(1.905,-0.635) 14(1.905,0.635) 19(5.715,-0.635) 20(5.715,0.635)
  silkscreen extent -6.39,-2.23 6.39,-1.32, body extent -6.35,-5.28 6.35,0.84, height 3.41
WE-HCI_5040 [mm] "SMD, 2-Leads, Body 5.5x5.3mm"
  rect 1.6x1.9 smd: 1(0,2.05) 2(0,-2.05)
  silkscreen extent -2.65,-2.75 2.65,2.75, body extent -2.65,-2.79 2.65,2.79, height 3.95

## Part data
C1: library part CMP-0009193-2, "CAP, CERM, 0.33 µF, 250 V, +/- 10%, X7R, 1210", Cap_Case=1210, Manufacturer=Kemet, Supplier Part Number 1=399-17953-1-ND, TempCo=X7R, Tolerance_%=10%, Value1=Unknown, Value2=250V, ValueDisplayed=0.33uF
C2: library part CMP-0006684-2, "CAP, CERM, 0.022 uF, 50 V, +/- 10%, X7R, 0402", Cap_Case=0402, Manufacturer=MuRata, Supplier Part Number 1=490-3884-1-ND, TempCo=X7R, Tolerance_%=10%, Value1=Unknown, Value2=50V, ValueDisplayed=0.022uF
C3 C15: library part CMP-0007040-4, "CAP, CERM, 1 µF, 25 V, +/- 10%, X7R, 0603", Cap_Case=0603, Manufacturer=TDK, Supplier Part Number 1=445-5956-1-ND, TempCo=X7R, Tolerance_%=10%, Value1=Unknown, Value2=25V, ValueDisplayed=1uF
C4: library part CMP-0091874-1, "270µF 16V Aluminum - Polymer Capacitors Radial, Can 10mOhm 20000 Hrs @ 105°C", Digikey Part Number=565-4812-ND, Leakage Current=864uA, Manufacturer="Nippon Chemi-Con", Mouser Part Number=661-APSG160E271MF08J, Operating Temperature Range="-55°C to +105°C", Tolerance_%=20%, ValueDisplayed=270uF
C5 C6 C7 C9 C11 C13: library part CMP-0008667-2, "CAP, CERM, 22 uF, 35 V, +/- 20%, X5R, 1206", Cap_Case=1206_180, Manufacturer=TDK, Supplier Part Number 1=445-8045-1-ND, TempCo=X5R, Tolerance_%=20%, Value1="0.002398 ohm", Value2=35V, ValueDisplayed=22uF
C8 C16 C19: library part CMP-0006659-2, "CAP, CERM, 0.1 uF, 25 V, +/- 10%, X7R, 0402", Cap_Case=0402, Manufacturer=MuRata, Supplier Part Number 1=490-10698-1-ND, TempCo=X7R, Tolerance_%=10%, Value1=Unknown, Value2=25V, ValueDisplayed=0.1uF
C10: library part CMP-0006439-2, "CAP, CERM, 22 pF, 50 V, +/- 5%, C0G/NP0, 0402", Cap_Case=0402, Manufacturer=MuRata, Supplier Part Number 1=81-GRM1555C1H220JA1D, TempCo=C0G/NP0, Tolerance_%=5%, Value1=Unknown, Value2=50V, ValueDisplayed=22pF
C12: library part CMP-0007009-5, "CAP, CERM, 10 µF, 35 V, +/- 10%, X5R, 0603", Cap_Case=0603, Manufacturer=Murata, TempCo=X5R, Tolerance_%=10%, Value1="0.004211 ohm", Value2=35V, ValueDisplayed=10uF
C14 C17 C21: library part CMP-0006410-2, "CAP, CERM, 100 pF, 50 V, +/- 5%, C0G/NP0, 0402", Cap_Case=0402, Manufacturer=MuRata, Supplier Part Number 1=81-GRM1555C1H101JA1D, TempCo=C0G/NP0, Tolerance_%=5%, Value1=Unknown, Value2=50V, ValueDisplayed=100pF
C18 C20: library part CMP-0006687-2, "CAP, CERM, 330 pF, 50 V, +/- 10%, X7R, 0402", Cap_Case=0402, Manufacturer=MuRata, Supplier Part Number 1=490-3247-1-ND, TempCo=X7R, Tolerance_%=10%, Value1=Unknown, Value2=50V, ValueDisplayed=330pF
C22: library part CMP-0006352-2, "CAP, CERM, 0.01 uF, 25 V, +/- 10%, X7R, 0402", Cap_Case=0402, Manufacturer=MuRata, Supplier Part Number 1=490-6043-2-ND, TempCo=X7R, Tolerance_%=10%, Value1=Unknown, Value2=25V, ValueDisplayed=0.01uF
C23: library part CMP-0006648-2, "CAP, CERM, 0.22 µF, 16 V, +/- 10%, X7R, 0402", Cap_Case=0402, Manufacturer=MuRata, Supplier Part Number 1=490-5418-1-ND, TempCo=X7R, Tolerance_%=10%, Value1=Unknown, Value2=16V, ValueDisplayed=0.22uF
C24: library part CMP-0009318-2, "CAP, CERM, 0.1 uF, 630 V, +/- 10%, X7R, 1808", Cap_Case=1808, Manufacturer=Kemet, Supplier Part Number 1=399-6515-1-ND, TempCo=X7R, Tolerance_%=10%, Value1=Unknown, Value2=630V, ValueDisplayed=0.1uF
D1 D2 D4 D5: library part CMP-0029150-2, "Diode, Switching, 200 V, 0.2 A, AEC-Q101, SOD-323", Manufacturer="ON Semiconductor", Value1=0.2A, Value2=1.25V
D3: library part CMP-0005821-3, "Diode, TVS, Bi, 16.2 V, SOD-323", Manufacturer=Toshiba, PartNumber=DF2B18FU,H3F, Value1=80W
J1: library part CMP-BK1, "Connector Socket Through Hole 17 position 0.050\" (1.27mm)", Current_A=1A, Digikey Part Number=GRPB171VWVN-RC-ND, Manufacturer="Sullins Connector Solutions", Operating Temperature Range="-40°C to +105°C", Part Number=GRPB171VWVN-RC
J2: library part CMP-0086278-1, "Header, 1.27mm, 4x2, Gold, R/A, TH", Current_A=1A, Manufacturer="Sullins Connector Solutions", Voltage_V=500V
J4: library part CMP-0054702-2, "Header, 50mil, 10x2, Gold, R/A, TH", Manufacturer="Sullins Connector Solutions", Supplier Part Number 1=S9017E-10-ND
J5 J7: library part CMP-0092135-1, Current_A=1A, Digikey Part Number=S9008E-04-ND, Manufacturer="Sullins Connector Solutions", Operating Temperature Range="-40°C to +125°C"
L1: library part CMP-0080751-1, "Inductor, Shielded, 1 µH, 11.5 A, 5.225 ohm, SMD", Manufacturer="Wurth Elektronik", Supplier Part Number 1=732-6176-1-ND, Value1="5.225 ohm", Value2=11.5A, ValueDisplayed=1µH
L2: library part CMP-0062695-1, "Inductor, Multilayer, Ferrite, 1 uH, 1.5 A, 0.208 ohm, SMD", Manufacturer=TDK, Supplier Part Number 1=445-6362-1-ND, Value1="0.208 ohm", Value2=1.5A, ValueDisplayed=1uH
LOGO1: library part CMP-0074835-1, "IEC 61010-1 High Voltage Warning"
Q1: library part CMP-0000587-1, "MOSFET, N-CH, 30 V, 60 A, DQG0008A (VSON-CLIP-8)", Alternate Manufacturer=None, Manufacturer="Texas Instruments", Supplier Part Number 1=296-39994-1-ND, Value1=0.003, Value2="23 nC"
Q2: library part CMP-0067574-1, "MOSFET, N-CH, 600 V, 0.021 A, AEC-Q101, SOT-23", Alternate Manufacturer=None, Manufacturer="Infineon Technologies", PartNumber=BSS126H6327XTSA2, Supplier Part Number 1=BSS126H6327XTSA2CT-ND, Value1="? ohm", Value2="1.4 nC"
Q3: library part CMP-0000485-2, "Transistor, NPN, 50 V, 0.1 A, AEC-Q101, SOT-416", Manufacturer="ON Semiconductor", Supplier Part Number 1=DTC114EET1GOSCT-ND, Value1="0.1 A", Value2=60
R1: library part CMP-0018673-3, "RES, 3.3 M, 5%, 0.25 W, AEC-Q200 Grade 0, 1206", Manufacturer=Vishay-Dale, Power_W=250mW, Supplier Part Number 1=541-3.3MECT-ND, TempCo="200 ppm/C", Tolerance_%=5%, Value2=0.25W, Value_Code=3M30, ValueDisplayed=3.3M
R2 R4: library part CMP-0081856-1, "RES, 0, 0%, 0.2 W, AEC-Q200 Grade 0, 0402", Manufacturer=Vishay-Dale, Power_W=200mW, Supplier Part Number 1=541-0.0YBTR-ND, Tolerance_%=0%, Value2=0.2W, Value_Code=0
R3: library part CMP-0017256-2, "RES, 0.01, 1%, 0.5 W, 1206", Manufacturer="Stackpole Electronics Inc", Power_W=500mW, Supplier Part Number 1=CSR1206FK10L0CT-ND, TempCo="100 ppm/C", Tolerance_%=1%, Value2=0.5W, Value_Code=R010, ValueDisplayed=0.01
R5 R9: library part CMP-0026436-2, "RES, 511, 1%, 0.063 W, AEC-Q200 Grade 0, 0402", Manufacturer=Vishay-Dale, Power_W=63mW, Supplier Part Number 1=541-511LCT-ND, TempCo="100 ppm/C", Tolerance_%=1%, Value2=0.063W, Value_Code=511R, ValueDisplayed=511
R6: library part CMP-0026294-2, "RES, 32.4 k, 1%, 0.063 W, AEC-Q200 Grade 0, 0402", Manufacturer=Vishay-Dale, Power_W=63mW, Supplier Part Number 1=541-32.4KLCT-ND, TempCo="100 ppm/C", Tolerance_%=1%, Value2=0.063W, Value_Code=32k4, ValueDisplayed=32.4k
R7 R10 R11: library part CMP-0025958-1, "RES, 10.0 k, 1%, 0.063 W, 0402", Manufacturer=Vishay-Dale, Power_W=63mW, Supplier Part Number 1=541-10.0KLCT-ND, TempCo="100 ppm/C", Tolerance_%=1%, Value2=0.063W, Value_Code=10k0, ValueDisplayed=10.0k
R8: library part CMP-0026620-3, "RES, 9.31 k, 1%, 0.063 W, AEC-Q200 Grade 0, 0402", Manufacturer=Vishay-Dale, Power_W=63mW, Supplier Part Number 1=541-9.31KLCT-ND, TempCo="100 ppm/C", Tolerance_%=1%, Value2=0.063W, Value_Code=9k31, ValueDisplayed=9.31k
R12: library part CMP-0027004-2, "RES, 0, 5%, 0.063 W, 0402", Manufacturer="Yageo America", Power_W=63mW, Supplier Part Number 1=311-0.0JRCT-ND, TempCo="200 ppm/C", Tolerance_%=5%, Value2=0.063W, Value_Code=0000, ValueDisplayed=0
R13: library part CMP-0026022-3, "RES, 150, 1%, 0.063 W, AEC-Q200 Grade 0, 0402", Manufacturer=Vishay-Dale, Power_W=63mW, Supplier Part Number 1=541-150LCT-ND, TempCo="100 ppm/C", Tolerance_%=1%, Value2=0.063W, Value_Code=150R, ValueDisplayed=150
R14: library part CMP-0026414-2, "RES, 4.99 k, 1%, 0.063 W, AEC-Q200 Grade 0, 0402", Manufacturer=Vishay-Dale, Power_W=63mW, Supplier Part Number 1=541-4.99KLCT-ND, TempCo="100 ppm/C", Tolerance_%=1%, Value2=0.063W, Value_Code=4k99, ValueDisplayed=4.99k
R15 R21: library part CMP-0026158-2, "RES, 200 k, 1%, 0.063 W, AEC-Q200 Grade 0, 0402", Manufacturer=Vishay-Dale, Power_W=63mW, Supplier Part Number 1=541-200KLCT-ND, TempCo="100 ppm/C", Tolerance_%=1%, Value2=0.063W, Value_Code=200k
R16: library part CMP-0026409-2, "RES, 4.42 k, 1%, 0.063 W, AEC-Q200 Grade 0, 0402", Manufacturer=Vishay-Dale, Power_W=63mW, Supplier Part Number 1=541-4.42KLCT-ND, TempCo="100 ppm/C", Tolerance_%=1%, Value2=0.063W, Value_Code=4k42, ValueDisplayed=4.42k
R17: library part CMP-0026162-2, "RES, 20.0 k, 1%, 0.063 W, AEC-Q200 Grade 0, 0402", Manufacturer=Vishay-Dale, Power_W=63mW, Supplier Part Number 1=541-20.0KLCT-ND, TempCo="100 ppm/C", Tolerance_%=1%, Value2=0.063W, Value_Code=20k0, ValueDisplayed=20.0k
R18: library part CMP-0026371-2, "RES, 41.2 k, 1%, 0.063 W, AEC-Q200 Grade 0, 0402", Manufacturer=Vishay-Dale, Power_W=63mW, Supplier Part Number 1=541-41.2KLCT-ND, TempCo="100 ppm/C", Tolerance_%=1%, Value2=0.063W, Value_Code=41k2, ValueDisplayed=41.2k
R19: library part CMP-0025950-3, "RES, 100 k, 1%, 0.063 W, AEC-Q200 Grade 0, 0402", Manufacturer=Vishay-Dale, Power_W=63mW, Supplier Part Number 1=541-100KLCT-ND, TempCo="100 ppm/C", Tolerance_%=1%, Value2=0.063W, Value_Code=100k
R20: library part CMP-0026282-2, "RES, 309 k, 1%, 0.063 W, AEC-Q200 Grade 0, 0402", Manufacturer=Vishay-Dale, Power_W=63mW, Supplier Part Number 1=541-309KLCT-ND, TempCo="100 ppm/C", Tolerance_%=1%, Value2=0.063W, Value_Code=309k
R22 R24 R25: library part CMP-0026822-3, "RES, 0, 5%, 0.063 W, AEC-Q200 Grade 0, 0402", Manufacturer=Vishay-Dale, Power_W=63mW, Supplier Part Number 1=541-0.0JCT-ND, TempCo="200 ppm/C", Tolerance_%=5%, Value2=0.063W, Value_Code=0000, ValueDisplayed=0
R23: library part CMP-0026605-2, "RES, 90.9 k, 1%, 0.063 W, AEC-Q200 Grade 0, 0402", Manufacturer=Vishay-Dale, Power_W=63mW, Supplier Part Number 1=541-90.9KLCT-ND, TempCo="100 ppm/C", Tolerance_%=1%, Value2=0.063W, Value_Code=90k9, ValueDisplayed=90.9k
RT1: library part CMP-0022434-4, "RES, 46.4 k, 1%, 0.1 W, AEC-Q200 Grade 0, 0603", Manufacturer=Vishay-Dale, Power_W=100mW, Supplier Part Number 1=541-46.4KHCT-ND, TempCo="100 ppm/C", Tolerance_%=1%, Value2=0.1W, Value_Code=46k4, ValueDisplayed=46.4k
U1: library part CMP-0092811-1, "Integrated 650-V GaN Half-Bridge for Active Clamp Flyback Converters", Manufacturer="Texas Instruments", Max Supply Voltage=26V, Min Supply Voltage=10V, Operating Temperature Range="-40°C to +125°C", Output Voltage=650V
U2: library part CMP-0063-01524-2, "High Side OR-ing FET Controller, 6-pin TSOT, 1000 Reel", Manufacturer="Texas Instruments", PackageTopMarking=SZHB*XTT, PowerWise=Y
U3: library part CMP-0086087-1, "UCC28782RTW, RTW0024B (WQFN-24)", Alternate Manufacturer="Texas Instruments"
U4: library part CMP-0032746-2, "Precision Micropower Shunt Voltage Reference, 1% accuracy, 5 V, 15 ppm / degC, 15 mA, -40 to 85 degC, 5-pin SC70 (DCK), Green (RoHS & no Sb/Br)", Manufacturer="Texas Instruments", Rating=Catalog, Temp Coeff(Max)(ppm/ degree C)=150, Temp Coeff(Typ)(ppm/ degree C)=15
U5: library part CMP-0087394-2, "Optoisolator Transistor Output 5000Vrms 1 Channel 6-SO", Manufacturer=Toshiba
U6: library part CMP-0040524-2, "MicroPower, Rail-to-Rail Output, General Purpose Operational Amplifier, 2.7 to 36 V, -40 to 125 degC, 5-pin SOT23 (DRL5), Green (RoHS & no Sb/Br)", Manufacturer="Texas Instruments", Rating=Catalog, Total Supply Voltage(Max)(+5V is 5, +/-5V is 10)=36, Total Supply Voltage(Min)(+5V is 5, +/-5V is 10)=2.7

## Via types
v1: diameter 0.65, hole 0.32, Top Layer to Bottom Layer, 44 vias
v2: diameter 0.5, hole 0.2, Top Layer to Bottom Layer, 5 vias
v3: diameter 0.65, hole 0.32, Top Layer to Bottom Layer, tented bottom, 4 vias

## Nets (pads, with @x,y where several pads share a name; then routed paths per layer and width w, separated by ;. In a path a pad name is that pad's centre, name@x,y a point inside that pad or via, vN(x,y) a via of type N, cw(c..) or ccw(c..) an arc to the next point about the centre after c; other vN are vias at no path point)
5VREF: Q3.1 R7.1 R19.2 U4.3 | length 6.6
  Bottom Layer w0.3: Q3.1@23.298,2.09 Q3.1@23.334,2.126 ; R19.2@23.334,2.941 Q3.1@23.334,2.126 ; R7.1@28.688,2.941 28.428,2.941 27.958,2.472 27.958,2.389 27.725,2.156 U4.3@26.583,2.156 23.364,2.156 Q3.1@23.334,2.126
15VSEC: J2.1 J5.3 | length 30.4
  Int2 (PWR) w1: 29.264,12.713 29.353,12.625 ; 29.328,15.1 29.333,15.1 29.835,15.602 ; J2.1@30.218,1.596 30.173,1.641 29.711,1.641 28.993,2.359 28.993,3.374 29.544,3.925 29.544,12.433 29.353,12.625 ; J5.3@31.105,28.617 31.105,27.611 29.835,26.341 29.835,15.602 ; 29.353,12.625 29.317,12.625 28.814,13.129 28.585,13.357 28.585,14.393 29.794,15.602 29.835,15.602
15VSEC_RTN: J2.3 J5.4 | length 32.3
  Int1 (GND) w0.6: 28.993,1.189 29.193,1.189 29.193,1.018 29.64,0.571 30.797,0.571 31.243,1.018 31.243,1.351 J2.3@31.488,1.596
  Int1 (GND) w1: 28.993,1.189 28.993,3.374 29.544,3.925 29.544,12.537 29.431,12.65 29.328,12.65 29.328,12.625 29.317,12.625 28.585,13.357 28.585,14.393 29.292,15.1 29.541,15.1 29.835,15.394 J5.4@29.835,28.617
CS: R9.1 R13.2 U1.31 | length 10.7
  Int1 (GND) w0.2: v1(8.646,18.449) 8.964,18.449 9.036,18.378 10.603,18.378 10.814,18.167 11.151,17.83 14.797,17.83 v1(14.986,17.641)
  Bottom Layer w0.2: U1.31@8.261,17.407 8.261,18.064 v1(8.646,18.449)
  Bottom Layer w0.25: v1(14.986,17.641) 14.986,16.975 15.386,16.575 R9.1@16.19,16.575 R13.2@16.19,15.816
FB: C18.1 R17.1 U3.6 | length 3
  Bottom Layer w0.25: U3.6@19.311,20.184 20.144,19.351 C18.1@20.144,18.555 R17.1@20.144,17.561
FLT: C21.1 RT1.1 U1.32 U3.1 | length 18.5
  Top Layer w0.4: v1(9.925,17.753) 9.925,19.622 14.747,24.444 17.474,24.444 v1(18.68,25.651)
  Bottom Layer w0.25: v1(18.68,25.651) 18.684,25.654 RT1.1@19.675,25.654 19.557,25.536 C21.1@19.557,24.444 19.311,24.198 U3.1@19.311,22.684
  Bottom Layer w0.4: U1.32@8.848,17.407 9.579,17.407 v1(9.925,17.753)
GND: C4.1 C5.1 C6.2 C8.2 C19.1 C22.2 J2.5 J2.7 J2.8 R3.2 R16.1 U2.2 U4.1 U6.2 | length 10.1
  Bottom Layer w0.2: C22.2@23.326,4.911 23.478,4.911 23.802,5.235 23.802,5.734 U6.2@23.834,5.766 v1(23.834,6.5) 23.826,6.508 C19.1@23.826,8.122
  Bottom Layer w0.3: R16.1@22.297,4.366 22.843,4.911 C22.2@23.326,4.911 ; C8.2@30.5,7.433 30.836,7.097 32.503,7.097 32.737,6.863 ; 32.737,6.862 33.062,6.537 U2.2@33.062,6.347 ; C6.2@33.102,4.654 33.102,3.792 J2.8@34.028,2.866
  other v1: 27.295,0.946 27.348,10.106 28.176,10.106 27.366,10.957 28.167,10.957
ICGND: C12.2 C15.1 C17.2 C20.1 C21.2 C23.2 R8.1 R13.1 R18.1 R21.1 R22.1 R23.1 R24.1 R25.2 U3.8 U3.17 U3.18 U3.20 U3.21 U3.22 U3.24 U3.25 U5.4 | length 14
  Top Layer w0.7: v1(12.069,7.622) 12.11,7.582 U5.4@12.11,6.699
  Int2 (PWR) w0.4: v1(12.069,7.622) 12.069,10.364 18.074,16.368 v1(18.074,17.023)
  Bottom Layer w0.3: C15.1@13.124,20.274 13.124,19.817 v1(13.631,19.31)
  other v1: 21.861,18.332 21.978,24.869 14.61,25.996
  other v2: 17.411,20.459 16.436,21.434 17.411,21.434 18.386,21.434 17.411,22.409
ISNS: J5.1 J5.2 J7.3 J7.4 R3.1 R20.1 | length 10
  Bottom Layer w0.2: R20.1@25.686,8.358 25.686,9.254 26.741,10.309 26.741,10.698 26.741,11.216 27.107,11.582 29.257,11.582 R3.1@30.331,12.656
  Bottom Layer w1: 30.47,13.875 J7.3@31.105,13.875
  Bottom Layer w1.1: J7.4@29.835,13.875 30.47,13.875 30.331,13.736 R3.1@30.331,12.656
